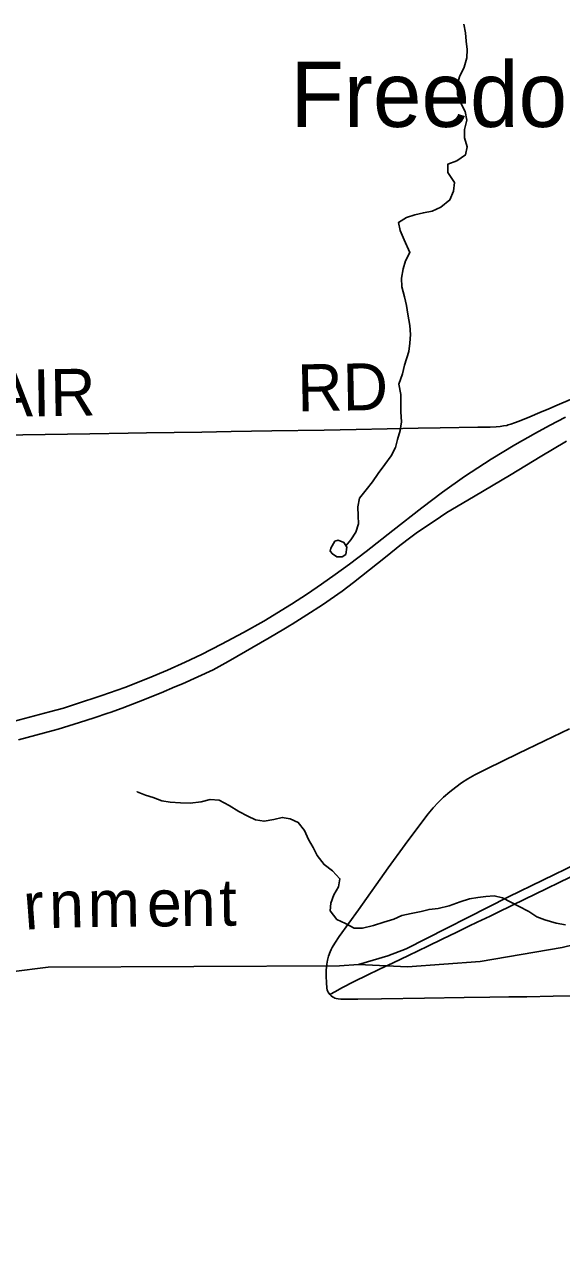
# Model space of a CAD drawing. Extents: x 0 to 34, y 0 to 22.
# Drawn here: x 12.669 to 14.293, y 8.341 to 12.039 of the extents above; entities that cross this region are included whole.
import ezdxf

# ---------------------------------------------------------------- set-up
doc = ezdxf.new("R2010")
doc.units = 0
for name, color, linetype in [('GM_X_Minor_Lake', 7, 'Continuous'), ('GM_X_Minor_River', 7, 'Continuous'), ('GM_X_Rail_Line', 7, 'Continuous'), ('GM_X_Rail_Line_Text', 7, 'Continuous'), ('GM_X_Township_Road', 7, 'Continuous'), ('GM_X_Township_Road_Text', 7, 'Continuous'), ('GM_X_Unincorporated_Text', 7, 'Continuous')]:
    doc.layers.add(name, color=color, linetype=linetype)

msp = doc.modelspace()

# ---------------------------------------------------------------- linework, layer by layer
at = {"layer": 'GM_X_Minor_Lake'}
msp.add_line((13.6073, 10.4747), (13.5952, 10.4536), dxfattribs=at)
msp.add_lwpolyline([(13.5952, 10.4536), (13.5934, 10.4451), (13.6002, 10.4366), (13.6135, 10.4273), (13.6296, 10.4275), (13.6409, 10.4352), (13.6435, 10.457), (13.6348, 10.4712), (13.6177, 10.4786), (13.6073, 10.4747)], dxfattribs=at)
at = {"layer": 'GM_X_Minor_River'}
for points in [[(13.9979, 12.0399), (14.0029, 12.0133), (14.0042, 11.9887), (14.0073, 11.9631), (14.0066, 11.9374), (13.9984, 11.9098), (13.9845, 11.8802), (13.9773, 11.8535), (13.9785, 11.827), (13.9883, 11.8005), (14.0018, 11.775), (14.0068, 11.7495), (13.9996, 11.7209), (13.9998, 11.6962), (14.0077, 11.6688), (14.0023, 11.644), (13.976, 11.6257), (13.9487, 11.6159), (13.9489, 11.5912), (13.9692, 11.5601), (13.9666, 11.5344), (13.9555, 11.5077), (13.9283, 11.4856), (13.902, 11.4739), (13.8755, 11.4688), (13.849, 11.4628), (13.8245, 11.4549), (13.8001, 11.4395), (13.8051, 11.4148)], [(13.8051, 11.4148), (13.8168, 11.3875), (13.8342, 11.3487), (13.8213, 11.3239), (13.814, 11.2991), (13.8086, 11.2706), (13.8098, 11.245), (13.8177, 11.2147), (13.8237, 11.1882), (13.8278, 11.1617), (13.8339, 11.1275), (13.836, 11.101), (13.8345, 11.0744), (13.831, 11.0487), (13.8182, 11.0077), (13.8118, 10.9811), (13.8008, 10.9506), (13.8068, 10.9193), (13.8074, 10.8662), (13.8087, 10.8358), (13.8052, 10.8102), (13.797, 10.7825), (13.7906, 10.7587), (13.7777, 10.7339), (13.759, 10.7071), (13.7385, 10.6803), (13.7217, 10.6544), (13.7021, 10.6305), (13.6816, 10.6056), (13.6771, 10.5789), (13.6784, 10.5514), (13.6787, 10.5277), (13.6704, 10.5029), (13.6555, 10.479), (13.6407, 10.4615)], [(14.3049, 9.3143), (14.2764, 9.3197), (14.2422, 9.3297), (14.2185, 9.3389), (14.1946, 9.3548), (14.1632, 9.3706), (14.1394, 9.3826), (14.1146, 9.3956), (14.089, 9.402), (14.0644, 9.3998), (14.0398, 9.3967), (14.0143, 9.3926), (13.986, 9.3837), (13.953, 9.3719), (13.9199, 9.3639), (13.8925, 9.3608), (13.868, 9.3548), (13.8387, 9.3488), (13.8103, 9.3427), (13.7859, 9.3311), (13.7557, 9.3222), (13.7245, 9.3123), (13.6915, 9.3043), (13.6659, 9.304), (13.6392, 9.318), (13.6135, 9.33), (13.5934, 9.3563), (13.595, 9.3801), (13.6042, 9.4049), (13.6181, 9.4288), (13.6226, 9.4535), (13.6005, 9.4779), (13.5747, 9.4966), (13.5536, 9.5239), (13.542, 9.5484), (13.5275, 9.5729), (13.5158, 9.5994), (13.4966, 9.6238), (13.4719, 9.6349), (13.4482, 9.6394), (13.4227, 9.6325), (13.3934, 9.6274), (13.3678, 9.6318), (13.344, 9.6429), (13.3173, 9.6569), (13.2877, 9.6755), (13.2573, 9.6913), (13.2307, 9.6938), (13.2033, 9.6868), (13.1702, 9.6827), (13.1409, 9.6833), (13.1096, 9.6858), (13.084, 9.6893), (13.0583, 9.6994), (13.0346, 9.7067), (13.0098, 9.7169), (13.0098, 9.7178)]]:
    msp.add_lwpolyline(points, dxfattribs=at)
at = {"layer": 'GM_X_Rail_Line'}
for points in [[(18.6712, 11.9797), (17.7965, 11.5996), (16.1817, 10.893), (16.1016, 10.8556), (16.0651, 10.819), (16.0291, 10.7614), (16.0117, 10.7238), (16.0013, 10.6748), (15.9912, 10.6032), (15.988, 10.4696), (15.9742, 10.4211), (15.9592, 10.364), (15.9356, 10.3204), (15.9074, 10.2808), (15.8654, 10.2415), (15.7943, 10.2063), (14.1322, 9.3985), (13.8231, 9.242), (13.7678, 9.2202), (13.679, 9.1945)], [(12.5923, 9.9184), (12.7448, 9.9584), (12.7863, 9.9703), (12.8226, 9.9816), (12.9031, 10.0078), (12.9727, 10.0328), (13.0456, 10.0612), (13.1013, 10.0847), (13.1545, 10.1095), (13.2037, 10.1325), (13.2645, 10.1631), (13.3314, 10.1985), (13.3931, 10.2334), (13.4765, 10.2842), (13.5245, 10.3159), (13.5674, 10.3449), (13.6081, 10.3739), (13.652, 10.4058), (13.7017, 10.4441), (13.7825, 10.5075), (13.8701, 10.5761), (13.9328, 10.6234), (13.9997, 10.6705), (14.0804, 10.7236), (14.1519, 10.7664), (14.2144, 10.8022), (14.2563, 10.8249), (14.3049, 10.8506)], [(13.679, 9.1945), (13.8272, 9.187), (14.0474, 9.2037), (14.2951, 9.2459), (14.3323, 9.2546)], [(13.679, 9.1945), (13.621, 9.1905), (12.7402, 9.186), (12.6286, 9.1722), (12.5249, 9.152), (12.4146, 9.1345), (12.3152, 9.1085), (12.0781, 9.0427), (11.1674, 8.8145), (10.5192, 8.6466), (10.4379, 8.6128), (10.3876, 8.5764), (10.3558, 8.5235), (10.3194, 8.4503), (10.3134, 8.3711), (10.3126, 8.279), (10.5396, 7.323), (10.674, 6.8202), (10.7391, 6.5291), (10.7656, 6.4088), (10.7761, 6.0767), (10.7857, 5.0468), (10.7878, 4.2991)]]:
    msp.add_lwpolyline(points, dxfattribs=at)
at = {"layer": 'GM_X_Township_Road'}
for points in [[(14.1314, 10.8269), (14.1392, 10.8292), (14.1505, 10.833), (14.1645, 10.8385), (14.197, 10.8517), (14.2271, 10.8641), (14.2543, 10.8755), (14.28, 10.8865), (14.32, 10.9034)], [(12.2808, 10.7916), (12.3191, 10.7916), (12.5174, 10.795), (12.5921, 10.7955), (12.6641, 10.7971), (12.8668, 10.7995), (12.9825, 10.8022), (13.0382, 10.8035), (13.2055, 10.8053), (13.2934, 10.8068), (13.4168, 10.8092), (13.5755, 10.8112), (13.672, 10.8129), (13.8598, 10.8171), (13.9255, 10.8183), (14.0403, 10.8199), (14.0775, 10.8205), (14.095, 10.8211), (14.1069, 10.8225), (14.1174, 10.824), (14.1273, 10.8257), (14.1314, 10.8269)], [(12.6507, 9.8745), (12.7554, 9.9019), (12.7703, 9.9062), (12.8347, 9.926), (12.8794, 9.9406), (12.9205, 9.9547), (12.9279, 9.9572), (12.9644, 9.9701), (13.0135, 9.9886), (13.0825, 10.0166), (13.1239, 10.0342), (13.1468, 10.0438), (13.2393, 10.0861), (13.2851, 10.111), (13.4091, 10.1827), (13.453, 10.209), (13.4637, 10.2153), (13.4716, 10.2202), (13.4783, 10.2243), (13.523, 10.2523), (13.5699, 10.2825), (13.63, 10.3241), (13.6643, 10.3499), (13.7365, 10.4073), (13.7653, 10.431), (13.8039, 10.4623), (13.8372, 10.4876), (13.8574, 10.5023), (13.8834, 10.52), (13.9268, 10.5493), (13.9465, 10.5617), (14.0265, 10.6097), (14.1406, 10.6773), (14.228, 10.7299), (14.3081, 10.7775)], [(13.5923, 9.1029), (13.589, 9.1074), (13.587, 9.1105), (13.5856, 9.1143), (13.5846, 9.1178), (13.5835, 9.1226), (13.5825, 9.1399), (13.5815, 9.1578), (13.5815, 9.1745), (13.5823, 9.1883), (13.5831, 9.1952), (13.5838, 9.2012), (13.5851, 9.2074), (13.5883, 9.2194), (13.5931, 9.2325), (13.5959, 9.2395), (13.5991, 9.2452), (13.6069, 9.2586), (13.6209, 9.2792), (13.6789, 9.3599), (13.7691, 9.4864), (13.8201, 9.5569), (13.87, 9.6244), (13.8901, 9.6501), (13.905, 9.668), (13.9198, 9.6839), (13.9364, 9.7002), (13.955, 9.7167), (13.9732, 9.7312), (13.9909, 9.7439), (14.0092, 9.7557), (14.0308, 9.7679), (14.0667, 9.7865), (14.1617, 9.8326), (14.2415, 9.871), (14.317, 9.9076)], [(13.5923, 9.1029), (13.6092, 9.1127), (13.6281, 9.1235), (13.6657, 9.1429), (13.7047, 9.1618), (13.7428, 9.1797), (13.7837, 9.1993), (13.8297, 9.2217), (13.8884, 9.2501), (13.9319, 9.2708), (13.9766, 9.2925), (14.0129, 9.31), (14.0382, 9.322), (14.0774, 9.3407), (14.1011, 9.3524), (14.1819, 9.3922), (14.2462, 9.4233), (14.2881, 9.4436), (14.3427, 9.47)], [(13.5923, 9.1029), (13.5964, 9.0992), (13.5999, 9.0963), (13.604, 9.0941), (13.6077, 9.0924), (13.6116, 9.0914), (13.6171, 9.0905), (13.6255, 9.0897), (13.6441, 9.0888), (13.6767, 9.089), (13.7482, 9.0905), (13.8788, 9.0926), (13.9984, 9.0941), (14.0761, 9.095), (14.1336, 9.096), (14.188, 9.0968), (14.2672, 9.0979), (14.3356, 9.099)]]:
    msp.add_lwpolyline(points, dxfattribs=at)

# ---------------------------------------------------------------- texts
at = {"layer": 'GM_X_Rail_Line_Text'}
for s, rotation, p in [('t', 0.5746, (13.2585, 9.3113)), ('r', 4.1862, (12.6703, 9.299)), ('n', 1.2686, (12.7446, 9.3045)), ('m', 0.6405, (12.8607, 9.3071)), ('e', 0.571, (13.0398, 9.3091)), ('n', 0.5699, (13.1419, 9.3101))]:
    msp.add_text(s, height=0.1416, rotation=rotation, dxfattribs=at).set_placement(p)
at = {"layer": 'GM_X_Township_Road_Text'}
for s, rotation, p in [('VAIR', 0.8423, (12.4414, 10.8492)), ('RD', 0.9809, (13.4949, 10.8679))]:
    msp.add_text(s, height=0.14205, rotation=rotation, dxfattribs=at).set_placement(p)
at = {"layer": 'GM_X_Unincorporated_Text'}
msp.add_text('Freedom Station', height=0.197443, rotation=0, dxfattribs=at).set_placement((13.4734, 11.7286))

doc.saveas('drawing.dxf')
